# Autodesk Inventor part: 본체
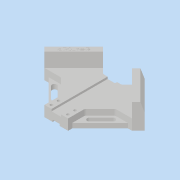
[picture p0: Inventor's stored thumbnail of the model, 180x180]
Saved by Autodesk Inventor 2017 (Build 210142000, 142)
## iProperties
Part Number: 본체
Material: 일반
Document SubType Name: Modeling
Designer: 222
Density: 1 g/cm^3
Appearance: 기본값
Author: 222
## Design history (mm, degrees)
sketch "스케치1"
  geometry: L1 (0, 149.706)-(-84.853, 64.853); L2 (-84.853, 64.853)-(0, -20); L3 (0, -20)-(0, 149.706); 1 further point
  constraints: 6 end point, 1 vertical, 1 vertical alignment
  dimensions: "d0" = 90 deg angle of L2 L1; "d1" = 45 deg angle of L3 L1; "d2" = 120 distance of L1.start L1.end; "d3" = 20 distance of point (0, 0) L2.end
extrude "돌출1" new body sketch "스케치1" distance "d4" = 18; taper "d5" = 0 deg
sketch "스케치2"
  geometry: L1 (-20, 0)-(-20, 28.284); L2 (-84.853, 64.853)-(0, -20) reference; L3 (-20, 28.284)-(-45.962, 54.246); L4 (-45.962, 54.246)-(-74.246, 54.246); L5 (-20, 7.071)-(-67.175, 54.246); L6 (-74.246, 54.246)-(-20, 0); 1 further point
  constraints: 10 end point, 4 point on line, 2 parallel, 1 collinear, 1 vertical
  dimensions: "d7" = 20 distance of point (0, 0) L1.start; "d11" = 15 distance of L4.end L2.start; "d12" = 20 distance between parallel lines of L2 L3; "d13" = 5 distance between parallel lines of L2 L5; "d14" = 135 deg angle of L3 L4
extrude "돌출2" cut sketch "스케치2" stored distance "d15" = 18; taper "d16" = 0 deg
extrude "돌출3" cut sketch "스케치2" distance "d17" = 10; taper "d18" = 0 deg
sketch "스케치3"
  geometry: L1 (-52.326, 49.296)-(-26.87, 23.841); L2 (-52.326, 43.64)-(-32.527, 23.841); L3 (-26.87, 29.497)-(-46.669, 49.296); L4 (-45.962, 54.246)-(-20, 28.284) reference; L5 (0, 149.706)-(-84.853, 64.853) reference; L6 (-84.853, 64.853)-(-74.246, 54.246) reference; A1 r 4 centre (-49.497, 46.468) between (-46.669, 49.296) and (-52.326, 43.64); A2 r 4 centre (-29.698, 26.669) between (-32.527, 23.841) and (-26.87, 29.497); 2 further points
  constraints: 8 end point, 6 point on circle, 4 tangent, 2 centre point, 2 parallel, 2 point on line, 1 midpoint
  dimensions: "d19" = 28 distance of A2.centre A1.centre; "d20" = 38 distance from line of A1.centre L5; "d21" = 12 distance from line of A1.centre L6; "d22" = 4 radius of A1
extrude "돌출4" cut sketch "스케치3" stored distance "d23" = 10; taper "d24" = 0 deg
sketch "스케치4"
  geometry: L1 (-20, 0)-(0, -20) reference; L2 (-20, 0)-(0, 0); L3 (0, 0)-(0, -20); L4 (0, -20)-(-20, -20); L5 (-20, -20)-(-20, 0); L6 (0, -20)-(0, 149.706) reference; 1 further point
  constraints: 8 end point, 2 parallel, 2 point on line, 1 horizontal, 1 perpendicular
extrude "돌출5" cut sketch "스케치4" stored distance "d25" = 10; taper "d26" = 0 deg
sketch "스케치5"
  geometry: L1 (-35.355, 114.35)-(-16.005, 95); L2 (-16.005, 95)-(0, 95); L3 (-20, 0)-(0, 0) reference; L4 (-84.853, 64.853)-(-74.246, 54.246) reference; L5 (0, 149.706)-(-84.853, 64.853) reference; L6 (0, 0)-(0, 149.706) reference; L7 (0, 95)-(0, 149.706)
  constraints: 6 end point, 1 collinear, 1 horizontal, 1 parallel, 1 point on line
  dimensions: "d27" = 95 distance between parallel lines of L2 L3; "d28" = 50 distance of L5.start L1.start
extrude "돌출6" cut sketch "스케치5" stored distance "d29" = 10; taper "d30" = 0 deg
sketch "스케치6"
  geometry: L1 (-84.853, 64.853)-(-35.355, 114.35); L2 (-35.355, 114.35)-(-24.749, 103.744); L3 (-24.749, 103.744)-(-74.246, 54.246); L4 (-74.246, 54.246)-(-84.853, 64.853); L5 (-35.355, 114.35)-(-84.853, 64.853) reference; 1 further point
  constraints: 8 end point, 3 equal length, 1 perpendicular
  dimensions: "d31" = 15 distance of L3.end L1.start
extrude "돌출7" join sketch "스케치6" distance "d32" = 24; taper "d33" = 0 deg
chamfer "모따기1" distance "d34" = 5; stored, may be unused: second distance "d35" = 15, angle "d36" = 45 deg
sketch "스케치7"
  geometry: L1 (0, 0)-(0, 95) reference; L2 (0, 95)-(-8, 95); L3 (-8, 95)-(-8, 0); L4 (-8, 0)-(0, 0); L5 (0, 0)-(0, 95)
  constraints: 8 end point, 2 parallel, 1 horizontal, 1 perpendicular
  dimensions: "d37" = 8 distance of L1.end L2.end
extrude "돌출8" cut sketch "스케치7" distance "d38" = 3.5; taper "d39" = 0 deg
sketch "스케치8"
  geometry: L1 (0, 0)-(6, 0); L2 (6, 0)-(6, 95); L3 (6, 95)-(0, 95); L4 (0, 95)-(0, 0); 1 further point
  constraints: 8 end point, 2 parallel, 1 coincident, 1 horizontal, 1 perpendicular
  dimensions: "d40" = 6 distance of L1.start L1.end
extrude "돌출9" cut sketch "스케치8" distance "d41" = 3; taper "d42" = 0 deg
sketch "스케치9"
  geometry: L1 (6, 0)-(0, 0) reference; 2 further points
  constraints: 1 vertical alignment
  dimensions: "d43" = 14 horizontal distance of point (14, 6) L1.end; "d44" = 6 distance from line of point (14, 6) L1; "d45" = 12 distance of point (14, 18) point (14, 6)
hole "구멍1" sketch "스케치9" at (14, 6), (14, 18) diameter "d46" = 4.5; stored, may be unused: countersink angle "d50" = 90 deg, drill point angle "d52" = 118 deg; dims "d47" = 6, "d48" = 8, "d49" = 10, "d51" = 8
sketch "스케치10"
  geometry: L1 (-31.82, 110.815)-(-35.355, 114.35) reference; L2 (-74.246, 54.246)-(-24.749, 103.744) reference; 2 further points
  constraints: 1 other
  dimensions: "d53" = 35 distance from line of point (-53.033, 82.53) L1; "d54" = 5 distance from line of L2 point (-53.033, 82.53)
feature "엠보싱1" sketch "스케치10" dims "d0" = 90 deg, "d1" = 45 deg, "d2" = 120, "d3" = 20, "d55" = 0.5, "d56" = 0
fillet "모깎기1" dims "d57" = 5
node "솔리드1"
mirror "미러1"
